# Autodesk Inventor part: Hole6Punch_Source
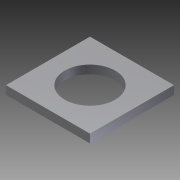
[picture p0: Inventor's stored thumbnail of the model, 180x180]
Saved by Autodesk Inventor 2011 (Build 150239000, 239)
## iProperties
Created: 2007-02
Part Number: Hole6Punch_Source
Material: Default
Document SubType Name: Sheet Metal
Designer: Autodesk, Inc.
Mass: 0.0717257 g
Surface Area: 2.02301 cm^2
Volume: 0.0717257 cm^3
Density: 1 g/cm^3
Sheet Metal Rule: 1 mm
Author: Autodesk, Inc.
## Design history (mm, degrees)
node "Face1"
  sketch "Sketch1"
    geometry: L1 (-5, 5)-(5, 5); L2 (5, 5)-(5, -5); L3 (5, -5)-(-5, -5); L4 (-5, -5)-(-5, 5); L5 (-5, 5)-(5, -5); 2 further points
    constraints: 10 end point, 2 parallel, 1 coincident, 1 horizontal, 1 midpoint, 1 perpendicular
    dimensions: "d0" = 10 distance of L2.end L3.end; "d1" = 10 distance of L1.end L2.end (= d0)
sketch "Sketch2"
  geometry: C1 r 3 at (0, 0); 2 further points
  constraints: 2 coincident, 1 centre point
  dimensions: "d3" = 6 diameter of C1
cut "Cut1" sketch "Sketch2" dims "d4" = 1 (= Thickness), "d5" = 0
body "Solid1"
face "Plate1" dims "Thickness" = 1
other parameters: "BendRadius" = 0.5, "BendReliefWidth" = 1 (= Thickness), "BendReliefDepth" = 0.5 (= 0.5 x Thickness), "CornerReliefSize" = 4 (= 4 x Thickness), "SeamGap" = 0.01, "MinimumRemnant" = 2 (= 2 x Thickness), "TransitionRadius" = 0.5 (= BendRadius), "JacobiRadiusSize" = 1 (= Thickness), "d2" = 0.5 (= BendRadius), "GapSize" = 1 (= Thickness)
